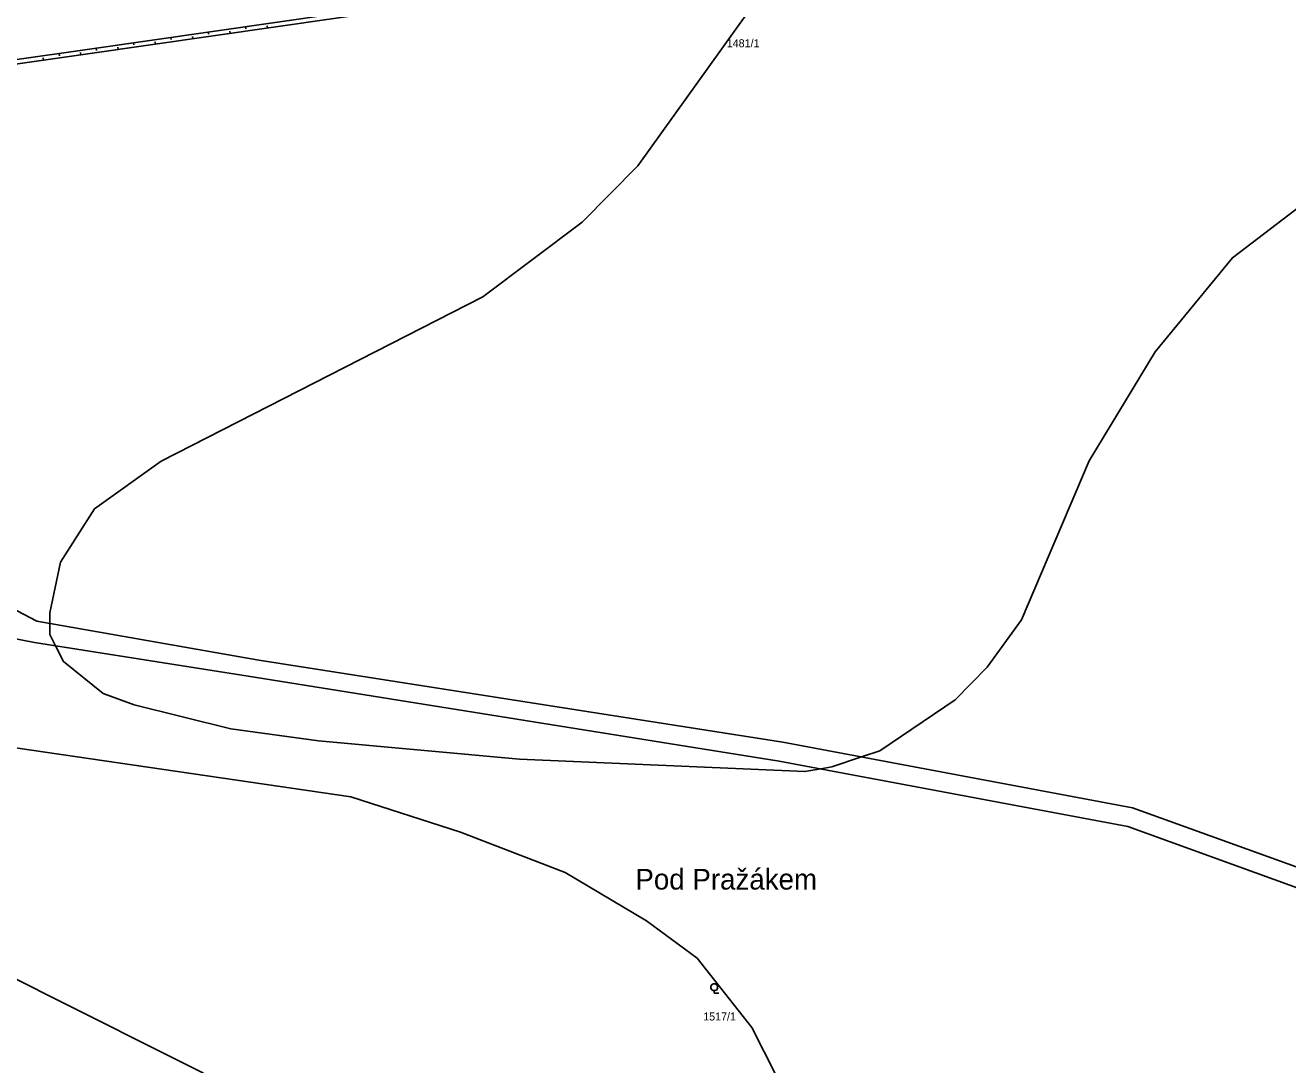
# Model space of a CAD drawing. Extents: x -779618 to -776429, y -1144546 to -1143350.
# Drawn here: x -777926.1 to -777658, y -1144325.3 to -1144104.5 of the extents above; entities that cross this region are included whole.
import ezdxf

# ---------------------------------------------------------------- set-up
doc = ezdxf.new("R2010")
doc.units = 0
for name, color, linetype in [('1', 7, 'Continuous'), ('11', 7, 'Continuous'), ('13', 7, 'Continuous'), ('2', 7, 'Continuous'), ('3', 7, 'Continuous'), ('7', 7, 'Continuous')]:
    doc.layers.add(name, color=color, linetype=linetype)

msp = doc.modelspace()

# ---------------------------------------------------------------- linework, layer by layer
at = {"layer": '1'}
for p, q in [((-777923.7, -1144231.09), (-777942.07, -1144221.33)), ((-777940.8, -1144232.44), (-777924.16, -1144235.57)), ((-777876.49, -1144239.35), (-777923.7, -1144231.09)), ((-777924.16, -1144235.57), (-777877.45, -1144242.98)), ((-777765.21, -1144256.79), (-777876.49, -1144239.35)), ((-777877.45, -1144242.98), (-777766.02, -1144260.79)), ((-777690.99, -1144270.7), (-777765.21, -1144256.79)), ((-777766.02, -1144260.79), (-777691.99, -1144274.68)), ((-777855.44, -1144343.58), (-778011.12, -1144265.48)), ((-777623.58, -1144295.09), (-777690.99, -1144270.7)), ((-777691.99, -1144274.68), (-777625.45, -1144298.8))]:
    msp.add_line(p, q, dxfattribs=at)
at = {"layer": '11'}
for points in [[(-777652.35, -1144140.64), (-777669.76, -1144153.87), (-777686.17, -1144173.83), (-777700.16, -1144197.01), (-777714.52, -1144230.77), (-777721.82, -1144240.87), (-777728.65, -1144247.79), (-777744.66, -1144258.6), (-777748.53, -1144259.92), (-777754.79, -1144262.04), (-777757.17, -1144262.45), (-777760.54, -1144263.03), (-777821.18, -1144260.4), (-777863.81, -1144256.52), (-777882.45, -1144253.92), (-777903.01, -1144248.88), (-777909.58, -1144246.46), (-777917.98, -1144239.66), (-777919.7, -1144236.28), (-777920.89, -1144233.93), (-777920.91, -1144231.58), (-777920.92, -1144229.27), (-777918.61, -1144218.53), (-777911.41, -1144207.23), (-777897.24, -1144197.06), (-777828.96, -1144162.14), (-777807.82, -1144146.28), (-777795.99, -1144134.3), (-777770.52, -1144098.7)], [(-777980.08, -1144250.42), (-777857.01, -1144268.43), (-777833.71, -1144275.88), (-777811.46, -1144284.49), (-777794.21, -1144294.72), (-777783.45, -1144302.7), (-777771.8, -1144317.41), (-777758.56, -1144343.51), (-777750.82, -1144365.57), (-777735.2, -1144432.89), (-777733.86, -1144438.65), (-777729.69, -1144456.62)]]:
    msp.add_lwpolyline(points, dxfattribs=at)
at = {"layer": '13'}
for p, q in [((-777879.36, -1144104.74), (-777879.29, -1144105.23)), ((-777874.71, -1144105.07), (-777874.78, -1144104.57)), ((-777895.19, -1144107.02), (-777895.12, -1144107.51)), ((-777890.55, -1144107.35), (-777890.62, -1144106.85)), ((-777887.28, -1144105.88), (-777887.21, -1144106.37)), ((-777882.63, -1144106.21), (-777882.7, -1144105.71)), ((-777914.3, -1144110.77), (-777914.37, -1144110.27)), ((-777911.03, -1144109.3), (-777910.96, -1144109.79)), ((-777906.38, -1144109.63), (-777906.45, -1144109.14)), ((-777903.11, -1144108.16), (-777903.04, -1144108.65)), ((-777898.47, -1144108.49), (-777898.54, -1144108)), ((-777922.22, -1144111.9), (-777922.29, -1144111.4)), ((-777918.95, -1144110.43), (-777918.88, -1144110.93))]:
    msp.add_line(p, q, dxfattribs=at)
msp.add_lwpolyline([(-778046.59, -1144128.79), (-778033.12, -1144126.83), (-778012.62, -1144123.84), (-778008.39, -1144123.22), (-777995.49, -1144121.34), (-777995.33, -1144119.26), (-777989.54, -1144118.09), (-777989.69, -1144120.5), (-777912.98, -1144109.58), (-777833.61, -1144098.15), (-777749.52, -1144086.03), (-777662.82, -1144073.66), (-777659.12, -1144079.91), (-777658.45, -1144096.57), (-777659.45, -1144096.61), (-777660.1, -1144080.21), (-777663.34, -1144074.74), (-777749.38, -1144087.01), (-777833.47, -1144099.13), (-777912.84, -1144110.56), (-777989.71, -1144121.51)], dxfattribs=at)
at = {"layer": '3'}
msp.add_lwpolyline([(-777779.81, -1144309.57), (-777780, -1144309.57), (-777780.34, -1144309.38), (-777780.53, -1144309.04), (-777780.53, -1144308.65), (-777780.34, -1144308.31), (-777780, -1144308.12), (-777779.61, -1144308.12), (-777779.27, -1144308.31), (-777779.08, -1144308.65), (-777779.08, -1144309.04), (-777779.27, -1144309.38), (-777779.61, -1144309.57), (-777779.8, -1144309.57), (-777779.8, -1144310.1), (-777778.8, -1144310.1)], dxfattribs=at)

# ---------------------------------------------------------------- texts
at = {"layer": '2'}
for s, p in [('1481/1', (-777777.14, -1144109.13)), ('1517/1', (-777782.14, -1144315.92))]:
    msp.add_text(s, height=1.7, dxfattribs=at).set_placement(p)
at = {"layer": '7'}
msp.add_text('Pod Pražákem', height=4.4, dxfattribs=at).set_placement((-777796.55, -1144288.1))

doc.saveas('drawing.dxf')
